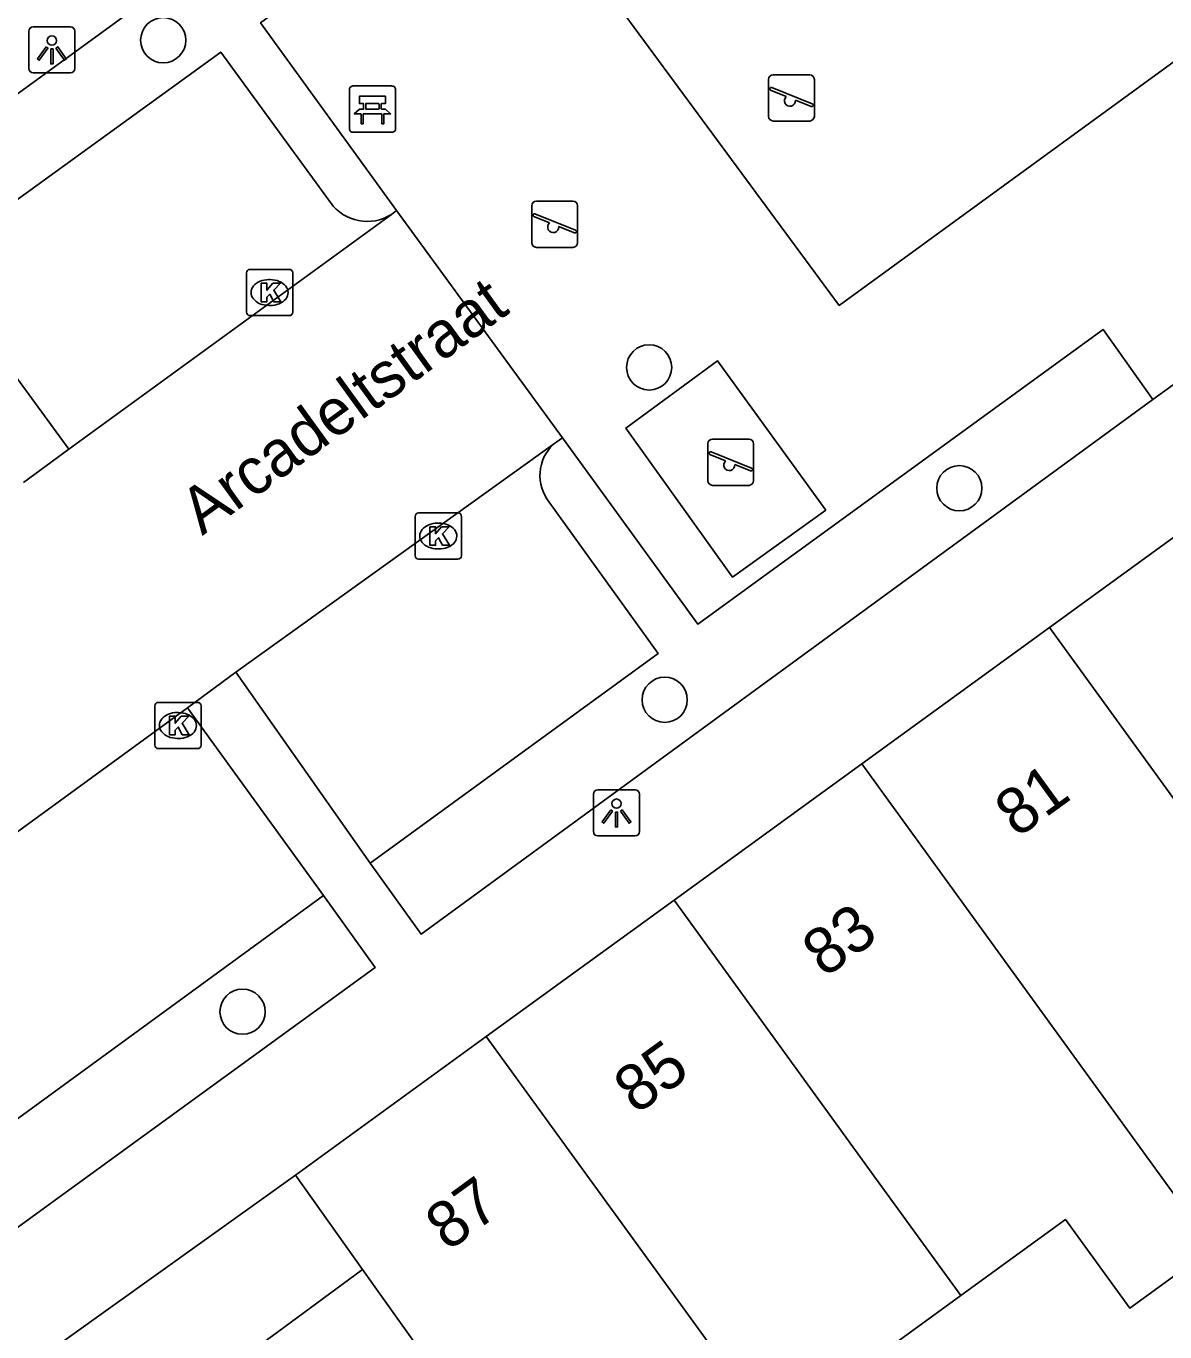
# Model space of a CAD drawing. Extents: x 159822 to 160765, y 380693 to 381634.
# Drawn here: x 159931.31 to 159955.93, y 381250 to 381278.23 of the extents above; entities that cross this region are included whole.
import ezdxf

# ---------------------------------------------------------------- set-up
doc = ezdxf.new("R2010")
doc.units = 0
for name, color, linetype in [('IMGEO_Bank', 7, 'Continuous'), ('IMGEO_Boom', 7, 'Continuous'), ('IMGEO_Kolk', 7, 'Continuous'), ('IMGEO_Lichtpunt', 7, 'Continuous'), ('IMGEO_Muur', 7, 'Continuous'), ('IMGEO_Openbare_ruimte_label', 7, 'Continuous'), ('IMGEO_Pand', 7, 'Continuous'), ('IMGEO_Pand_nummerreeks', 7, 'Continuous'), ('IMGEO_Parkeervlak_open', 7, 'Continuous'), ('IMGEO_Rijbaan_lokaal_open', 7, 'Continuous'), ('IMGEO_Speelvoorziening', 7, 'Continuous'), ('IMGEO_Voetpad_open', 7, 'Continuous')]:
    doc.layers.add(name, color=color, linetype=linetype)

msp = doc.modelspace()

# ---------------------------------------------------------------- linework, layer by layer
at = {"layer": 'IMGEO_Bank'}
for p, q in [((159938.299, 381276.01), (159938.299, 381276.851)), ((159938.299, 381276.851), (159938.299, 381276.01)), ((159938.374, 381276.935), (159939.215, 381276.935)), ((159939.215, 381276.935), (159938.374, 381276.935)), ((159939.299, 381276.86), (159939.299, 381276.019)), ((159939.299, 381276.019), (159939.299, 381276.86)), ((159938.608, 381276.441), (159938.608, 381276.547)), ((159938.652, 381276.547), (159938.652, 381276.441)), ((159938.94, 381276.553), (159938.658, 381276.553)), ((159938.946, 381276.441), (159938.946, 381276.547)), ((159938.99, 381276.547), (159938.99, 381276.441)), ((159938.996, 381276.333), (159938.603, 381276.333)), ((159938.658, 381276.435), (159938.94, 381276.435)), ((159939.224, 381275.935), (159938.383, 381275.935)), ((159938.383, 381275.935), (159939.224, 381275.935))]:
    msp.add_line(p, q, dxfattribs=at)
for points in [[(159938.602, 381276.553), (159938.516, 381276.553), (159938.516, 381276.714), (159939.079, 381276.714), (159939.079, 381276.553), (159938.996, 381276.553)], [(159938.546, 381276.333), (159938.404, 381276.333), (159938.516, 381276.435), (159938.602, 381276.435)], [(159938.596, 381276.326), (159938.596, 381276.119), (159938.553, 381276.119), (159938.553, 381276.326)], [(159938.996, 381276.435), (159939.079, 381276.435), (159939.191, 381276.333), (159939.052, 381276.333)], [(159939.046, 381276.326), (159939.046, 381276.119), (159939.002, 381276.119), (159939.002, 381276.326)]]:
    msp.add_lwpolyline(points, dxfattribs=at)
for centre, radius, start, end in [((159938.377, 381276.857), 0.0779, 92.4484, 184.2845), ((159938.377, 381276.857), 0.0779, 92.4484, 184.2845), ((159939.221, 381276.857), 0.0779, 2.4484, 94.2845), ((159939.221, 381276.857), 0.0779, 2.4484, 94.2845), ((159938.601, 381276.546), 0.00671, 2.8957, 87.1043), ((159938.658, 381276.546), 0.00671, 92.8957, 177.1043), ((159938.94, 381276.546), 0.00671, 2.8957, 87.1043), ((159938.997, 381276.546), 0.00671, 92.8957, 177.1043), ((159938.546, 381276.326), 0.00671, 2.8957, 87.1043), ((159938.603, 381276.326), 0.00671, 92.8957, 177.1043), ((159938.601, 381276.442), 0.00671, 272.8957, 357.1043), ((159938.658, 381276.442), 0.00671, 182.8957, 267.1043), ((159938.94, 381276.442), 0.00671, 272.8957, 357.1043), ((159938.997, 381276.442), 0.00671, 182.8957, 267.1043), ((159938.995, 381276.326), 0.00671, 2.8957, 87.1043), ((159939.052, 381276.326), 0.00671, 92.8957, 177.1043), ((159938.377, 381276.013), 0.0779, 182.4484, 274.2845), ((159938.377, 381276.013), 0.0779, 182.4484, 274.2845), ((159939.221, 381276.013), 0.0779, 272.4484, 4.2845), ((159939.221, 381276.013), 0.0779, 272.4484, 4.2845)]:
    msp.add_arc(centre, radius, start, end, dxfattribs=at)
at = {"layer": 'IMGEO_Boom'}
for centre in [(159934.274, 381277.924), (159944.782, 381270.852), (159951.489, 381268.241), (159945.118, 381263.668), (159935.989, 381256.926)]:
    msp.add_circle(centre, 0.489, dxfattribs=at)
at = {"layer": 'IMGEO_Kolk'}
for p, q in [((159936.073, 381272.045), (159936.073, 381272.897)), ((159936.148, 381272.971), (159937, 381272.971)), ((159937.074, 381272.897), (159937.074, 381272.045)), ((159936.561, 381272.751), (159936.586, 381272.751)), ((159937, 381271.971), (159936.148, 381271.971)), ((159936.584, 381272.191), (159936.559, 381272.191)), ((159939.721, 381266.781), (159939.721, 381267.633)), ((159939.796, 381267.707), (159940.648, 381267.707)), ((159940.209, 381267.487), (159940.234, 381267.487)), ((159940.722, 381267.633), (159940.722, 381266.781)), ((159940.232, 381266.927), (159940.207, 381266.927)), ((159940.648, 381266.707), (159939.796, 381266.707)), ((159934.091, 381262.686), (159934.091, 381263.538)), ((159934.166, 381263.612), (159935.018, 381263.612)), ((159935.092, 381263.538), (159935.092, 381262.686)), ((159934.579, 381263.392), (159934.604, 381263.392)), ((159934.602, 381262.832), (159934.577, 381262.832)), ((159935.018, 381262.612), (159934.166, 381262.612))]:
    msp.add_line(p, q, dxfattribs=at)
for points in [[(159936.073, 381272.045), (159936.073, 381272.897)], [(159936.148, 381272.971), (159937, 381272.971)], [(159937.074, 381272.897), (159937.074, 381272.045)], [(159936.394, 381272.671), (159936.517, 381272.671), (159936.517, 381272.52), (159936.647, 381272.671), (159936.811, 381272.671), (159936.665, 381272.52), (159936.818, 381272.271), (159936.666, 381272.271), (159936.581, 381272.435), (159936.517, 381272.368), (159936.517, 381272.271), (159936.394, 381272.271), (159936.394, 381272.671)], [(159937, 381271.971), (159936.148, 381271.971)], [(159939.721, 381266.781), (159939.721, 381267.633)], [(159939.796, 381267.707), (159940.648, 381267.707)], [(159940.722, 381267.633), (159940.722, 381266.781)], [(159940.042, 381267.407), (159940.165, 381267.407), (159940.165, 381267.256), (159940.295, 381267.407), (159940.459, 381267.407), (159940.313, 381267.256), (159940.466, 381267.007), (159940.314, 381267.007), (159940.229, 381267.171), (159940.165, 381267.104), (159940.165, 381267.007), (159940.042, 381267.007), (159940.042, 381267.407)], [(159940.648, 381266.707), (159939.796, 381266.707)], [(159934.091, 381262.686), (159934.091, 381263.538)], [(159934.166, 381263.612), (159935.018, 381263.612)], [(159935.092, 381263.538), (159935.092, 381262.686)], [(159934.412, 381263.312), (159934.535, 381263.312), (159934.535, 381263.161), (159934.665, 381263.312), (159934.829, 381263.312), (159934.683, 381263.161), (159934.836, 381262.912), (159934.684, 381262.912), (159934.599, 381263.076), (159934.535, 381263.009), (159934.535, 381262.912), (159934.412, 381262.912), (159934.412, 381263.312)], [(159935.018, 381262.612), (159934.166, 381262.612)]]:
    msp.add_lwpolyline(points, dxfattribs=at)
for centre, start, end in [((159936.15, 381272.895), 91.552, 178.448), ((159936.15, 381272.895), 91.552, 178.448), ((159936.998, 381272.895), 1.552, 88.448), ((159936.998, 381272.895), 1.552, 88.448), ((159936.15, 381272.047), 181.552, 268.448), ((159936.15, 381272.047), 181.552, 268.448), ((159936.998, 381272.047), 271.552, 358.448), ((159936.998, 381272.047), 271.552, 358.448), ((159939.798, 381267.631), 91.552, 178.448), ((159939.798, 381267.631), 91.552, 178.448), ((159940.646, 381267.631), 1.552, 88.448), ((159940.646, 381267.631), 1.552, 88.448), ((159939.798, 381266.783), 181.552, 268.448), ((159939.798, 381266.783), 181.552, 268.448), ((159940.646, 381266.783), 271.552, 358.448), ((159940.646, 381266.783), 271.552, 358.448), ((159934.168, 381263.536), 91.552, 178.448), ((159934.168, 381263.536), 91.552, 178.448), ((159935.016, 381263.536), 1.552, 88.448), ((159935.016, 381263.536), 1.552, 88.448), ((159934.168, 381262.688), 181.552, 268.448), ((159934.168, 381262.688), 181.552, 268.448), ((159935.016, 381262.688), 271.552, 358.448), ((159935.016, 381262.688), 271.552, 358.448)]:
    msp.add_arc(centre, 0.0765, start, end, dxfattribs=at)
for centre, major_axis, ratio, start_param, end_param in [((159936.56, 381272.471), (-0.387, 0.002), 0.722429, 4.712389, 7.853982), ((159936.585, 381272.471), (-0.39, 0.002), 0.717154, 1.570796, 4.712389), ((159940.208, 381267.207), (-0.387, 0.002), 0.722429, 4.712389, 7.853982), ((159940.233, 381267.207), (-0.39, 0.002), 0.717154, 1.570796, 4.712389), ((159934.578, 381263.112), (-0.387, 0.002), 0.722429, 4.712389, 7.853982), ((159934.603, 381263.112), (-0.39, 0.002), 0.717154, 1.570796, 4.712389)]:
    msp.add_ellipse(centre, major_axis=major_axis, ratio=ratio, start_param=start_param, end_param=end_param, dxfattribs=at)
at = {"layer": 'IMGEO_Lichtpunt'}
for p, q in [((159932.27, 381278.214), (159931.462, 381278.214)), ((159932.27, 381278.214), (159931.462, 381278.214)), ((159931.368, 381278.119), (159931.368, 381277.312)), ((159931.368, 381278.119), (159931.368, 381277.312)), ((159932.364, 381277.312), (159932.364, 381278.119)), ((159932.364, 381277.312), (159932.364, 381278.119)), ((159931.462, 381277.218), (159932.27, 381277.218)), ((159931.462, 381277.218), (159932.27, 381277.218)), ((159943.576, 381261.626), (159943.576, 381260.819)), ((159943.576, 381261.626), (159943.576, 381260.819)), ((159944.478, 381261.721), (159943.67, 381261.721)), ((159944.478, 381261.721), (159943.67, 381261.721)), ((159944.572, 381260.819), (159944.572, 381261.626)), ((159944.572, 381260.819), (159944.572, 381261.626)), ((159943.67, 381260.725), (159944.478, 381260.725)), ((159943.67, 381260.725), (159944.478, 381260.725))]:
    msp.add_line(p, q, dxfattribs=at)
for points in [[(159931.742, 381277.783), (159931.781, 381277.755), (159931.593, 381277.493), (159931.555, 381277.52), (159931.742, 381277.783)], [(159931.844, 381277.735), (159931.891, 381277.735), (159931.891, 381277.413), (159931.844, 381277.413), (159931.844, 381277.735)], [(159931.954, 381277.755), (159931.992, 381277.782), (159932.179, 381277.52), (159932.14, 381277.492), (159931.954, 381277.755)], [(159943.95, 381261.29), (159943.989, 381261.262), (159943.801, 381261), (159943.763, 381261.027), (159943.95, 381261.29)], [(159944.052, 381261.242), (159944.099, 381261.242), (159944.099, 381260.92), (159944.052, 381260.92), (159944.052, 381261.242)], [(159944.162, 381261.262), (159944.2, 381261.289), (159944.387, 381261.027), (159944.348, 381260.999), (159944.162, 381261.262)]]:
    msp.add_lwpolyline(points, dxfattribs=at)
for centre in [(159931.867, 381277.917), (159944.075, 381261.424)]:
    msp.add_circle(centre, 0.0994, dxfattribs=at)
for centre, start, end in [((159931.462, 381278.119), 90, 180), ((159931.462, 381278.119), 90, 180), ((159932.27, 381278.119), 0, 90), ((159932.27, 381278.119), 0, 90), ((159931.462, 381277.312), 180, 270), ((159931.462, 381277.312), 180, 270), ((159932.27, 381277.312), 270, 0), ((159932.27, 381277.312), 270, 360), ((159943.67, 381261.626), 90, 180), ((159943.67, 381261.626), 90, 180), ((159944.478, 381261.626), 0, 90), ((159944.478, 381261.626), 0, 90), ((159943.67, 381260.819), 180, 270), ((159943.67, 381260.819), 180, 270), ((159944.478, 381260.819), 270, 0), ((159944.478, 381260.819), 270, 360)]:
    msp.add_arc(centre, 0.0946, start, end, dxfattribs=at)
at = {"layer": 'IMGEO_Muur'}
msp.add_lwpolyline([(159937.133, 381253.394), (159932.15, 381249.827), (159931.92, 381248.398)], dxfattribs=at)
at = {"layer": 'IMGEO_Pand'}
for points in [[(159953.441, 381265.229), (159957.5, 381268.175)], [(159949.38, 381262.281), (159953.441, 381265.229)], [(159953.441, 381265.229), (159957.82, 381259.193), (159959.617, 381256.717)], [(159945.32, 381259.335), (159949.38, 381262.281)], [(159956.968, 381251.824), (159949.38, 381262.281)], [(159941.26, 381256.389), (159945.32, 381259.335)], [(159951.521, 381250.79), (159949.7, 381253.299), (159945.32, 381259.335)], [(159937.133, 381253.394), (159941.26, 381256.389)], [(159941.26, 381256.389), (159945.896, 381250), (159948.828, 381245.959), (159948.928, 381245.822)], [(159937.133, 381253.394), (159938.586, 381251.354)], [(159956.968, 381251.824), (159955.173, 381250.521), (159953.784, 381252.435), (159951.521, 381250.79)], [(159938.586, 381251.354), (159936.742, 381250), (159934.579, 381248.412), (159938.817, 381242.456), (159937.076, 381241.217)], [(159943.122, 381244.977), (159942.866, 381245.337), (159939.55, 381250), (159938.586, 381251.354)], [(159951.521, 381250.79), (159950.433, 381250), (159949.357, 381249.218), (159950.817, 381247.166)]]:
    msp.add_lwpolyline(points, dxfattribs=at)
at = {"layer": 'IMGEO_Parkeervlak_open'}
for points in [[(159937.889, 381274.416), (159935.518, 381277.669), (159929.263, 381273.143)], [(159942.623, 381267.94), (159944.98, 381264.669), (159938.747, 381260.139)], [(159937.737, 381259.439), (159929.463, 381253.408), (159927.099, 381256.616)]]:
    msp.add_lwpolyline(points, dxfattribs=at)
for centre, radius, start, end in [((159938.686, 381274.991), 0.983, 215.7894, 302.2916), ((159943.347, 381268.518), 0.926, 133.2694, 218.5984)]:
    msp.add_arc(centre, radius, start, end, dxfattribs=at)
at = {"layer": 'IMGEO_Rijbaan_lokaal_open'}
for points in [[(159939.211, 381274.16), (159939.322, 381274.241)], [(159939.322, 381274.241), (159942.909, 381269.333)], [(159932.23, 381269.083), (159939.211, 381274.16)], [(159942.712, 381269.192), (159935.848, 381264.263)], [(159942.909, 381269.333), (159942.712, 381269.192)], [(159931.251, 381268.362), (159932.23, 381269.083)], [(159935.848, 381264.263), (159934.796, 381263.495)], [(159934.796, 381263.495), (159925.878, 381256.995)]]:
    msp.add_lwpolyline(points, dxfattribs=at)
at = {"layer": 'IMGEO_Speelvoorziening'}
for p, q in [((159947.364, 381276.278), (159947.364, 381277.078)), ((159947.364, 381277.078), (159947.364, 381276.278)), ((159947.464, 381277.178), (159948.254, 381277.178)), ((159948.254, 381277.178), (159947.464, 381277.178)), ((159948.354, 381277.078), (159948.354, 381276.278)), ((159948.354, 381276.278), (159948.354, 381277.078)), ((159947.747, 381276.706), (159947.408, 381276.843)), ((159947.433, 381276.903), (159948.309, 381276.55)), ((159948.285, 381276.49), (159947.945, 381276.627)), ((159948.254, 381276.178), (159947.464, 381276.178)), ((159947.464, 381276.178), (159948.254, 381276.178)), ((159942.244, 381273.547), (159942.244, 381274.347)), ((159942.244, 381274.347), (159942.244, 381273.547)), ((159942.344, 381274.447), (159943.134, 381274.447)), ((159943.134, 381274.447), (159942.344, 381274.447)), ((159943.234, 381274.347), (159943.234, 381273.547)), ((159943.234, 381273.547), (159943.234, 381274.347)), ((159942.627, 381273.975), (159942.288, 381274.112)), ((159942.313, 381274.172), (159943.189, 381273.819)), ((159943.165, 381273.759), (159942.825, 381273.896)), ((159943.134, 381273.447), (159942.344, 381273.447)), ((159942.344, 381273.447), (159943.134, 381273.447)), ((159946.051, 381268.403), (159946.051, 381269.203)), ((159946.051, 381269.203), (159946.051, 381268.403)), ((159946.151, 381269.303), (159946.941, 381269.303)), ((159946.941, 381269.303), (159946.151, 381269.303)), ((159947.041, 381269.203), (159947.041, 381268.403)), ((159947.041, 381268.403), (159947.041, 381269.203)), ((159946.434, 381268.831), (159946.095, 381268.968)), ((159946.12, 381269.028), (159946.996, 381268.675)), ((159946.972, 381268.615), (159946.632, 381268.752)), ((159946.941, 381268.303), (159946.151, 381268.303)), ((159946.151, 381268.303), (159946.941, 381268.303))]:
    msp.add_line(p, q, dxfattribs=at)
for centre, radius, start, end in [((159947.464, 381277.078), 0.1, 90, 180), ((159947.464, 381277.078), 0.1, 90, 180), ((159948.254, 381277.078), 0.1, 0, 90), ((159948.254, 381277.078), 0.1, 360, 90), ((159947.421, 381276.873), 0.0327, 68.078, 248.078), ((159947.826, 381276.616), 0.12, 130.9928, 5.1632), ((159948.297, 381276.52), 0.0327, 248.078, 68.078), ((159947.464, 381276.278), 0.1, 180, 270), ((159947.464, 381276.278), 0.1, 180, 270), ((159948.254, 381276.278), 0.1, 270, 0), ((159948.254, 381276.278), 0.1, 270, 0), ((159942.344, 381274.347), 0.1, 90, 180), ((159942.344, 381274.347), 0.1, 90, 180), ((159943.134, 381274.347), 0.1, 0, 90), ((159943.134, 381274.347), 0.1, 360, 90), ((159942.301, 381274.142), 0.0327, 68.078, 248.078), ((159942.706, 381273.885), 0.12, 130.9928, 5.1632), ((159943.177, 381273.789), 0.0327, 248.078, 68.078), ((159942.344, 381273.547), 0.1, 180, 270), ((159942.344, 381273.547), 0.1, 180, 270), ((159943.134, 381273.547), 0.1, 270, 0), ((159943.134, 381273.547), 0.1, 270, 0), ((159946.151, 381269.203), 0.1, 90, 180), ((159946.151, 381269.203), 0.1, 90, 180), ((159946.941, 381269.203), 0.1, 0, 90), ((159946.941, 381269.203), 0.1, 360, 90), ((159946.108, 381268.998), 0.0327, 68.078, 248.078), ((159946.513, 381268.741), 0.12, 130.9928, 5.1632), ((159946.984, 381268.645), 0.0327, 248.078, 68.078), ((159946.151, 381268.403), 0.1, 180, 270), ((159946.151, 381268.403), 0.1, 180, 270), ((159946.941, 381268.403), 0.1, 270, 0), ((159946.941, 381268.403), 0.1, 270, 0)]:
    msp.add_arc(centre, radius, start, end, dxfattribs=at)
at = {"layer": 'IMGEO_Voetpad_open'}
for points in [[(159929.263, 381273.143), (159928.168, 381274.619), (159943.953, 381286.112)], [(159943.953, 381286.112), (159945.034, 381284.633), (159936.378, 381278.301), (159939.322, 381274.241)], [(159953.428, 381286.065), (159943.829, 381279.059), (159948.891, 381272.191), (159958.469, 381279.172), (159953.428, 381286.065)], [(159932.23, 381269.083), (159929.263, 381273.143)], [(159942.909, 381269.333), (159945.837, 381265.301), (159954.597, 381271.672), (159955.676, 381270.159)], [(159957.647, 381271.588), (159955.676, 381270.159)], [(159948.603, 381267.768), (159946.586, 381266.321), (159944.28, 381269.539), (159946.26, 381270.991), (159948.603, 381267.768)], [(159955.676, 381270.159), (159939.851, 381258.605), (159938.747, 381260.139)], [(159938.747, 381260.139), (159935.848, 381264.263)], [(159934.796, 381263.495), (159937.737, 381259.439)], [(159929.93, 381251.403), (159930.588, 381251.88), (159938.857, 381257.878), (159937.737, 381259.439)], [(159932.15, 381249.827), (159937.133, 381253.394)]]:
    msp.add_lwpolyline(points, dxfattribs=at)

# ---------------------------------------------------------------- texts
at = {"layer": 'IMGEO_Openbare_ruimte_label'}
msp.add_text('Arcadeltstraat', height=1, rotation=35.9642, dxfattribs=at).set_placement((159935.118, 381267.206))
at = {"layer": 'IMGEO_Pand_nummerreeks'}
for s, p in [('81', (159952.741, 381260.667)), ('83', (159948.576, 381257.645)), ('85', (159944.502, 381254.689)), ('87', (159940.428, 381251.732))]:
    msp.add_text(s, height=1, rotation=35.9687, dxfattribs=at).set_placement(p)

doc.saveas('drawing.dxf')
